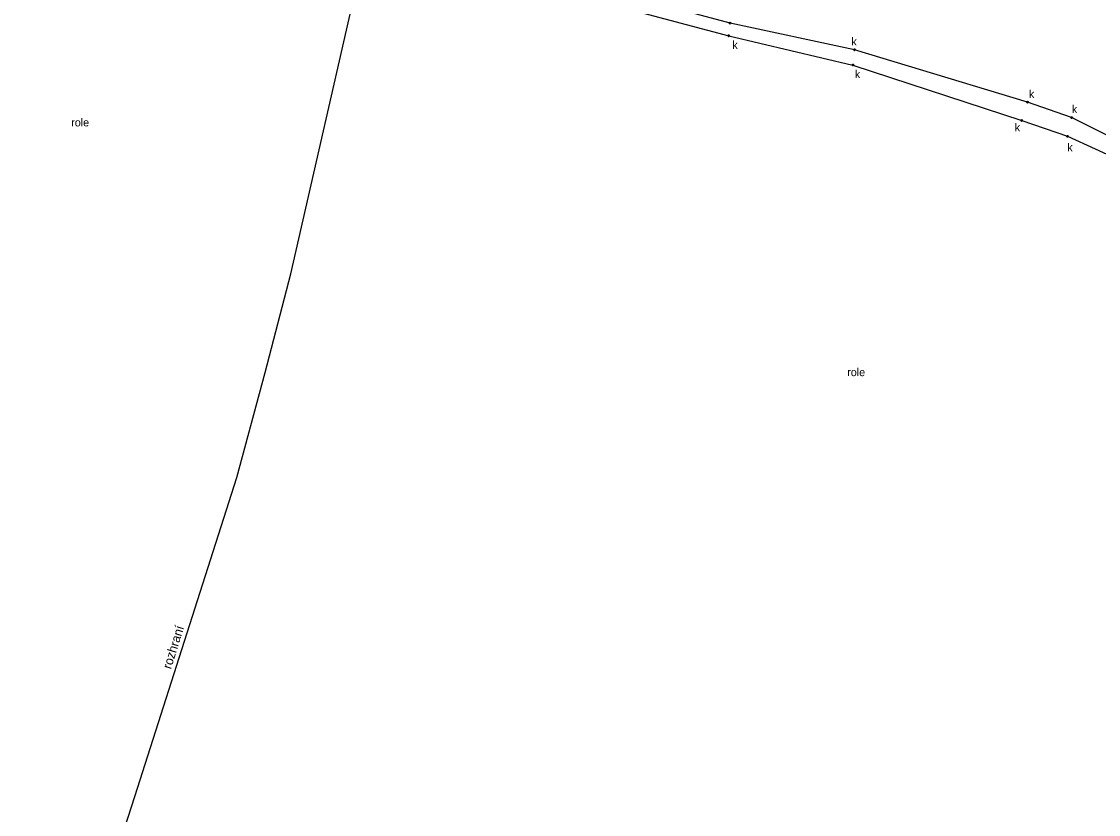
# Model space of a CAD drawing. Extents: x -661586 to -658793, y -1053889 to -1051031.
# Drawn here: x -661409.8 to -661006, y -1052972.2 to -1052674.7 of the extents above; entities that cross this region are included whole.
import ezdxf

# ---------------------------------------------------------------- set-up
doc = ezdxf.new("R2010")
doc.units = 0
for name, color, linetype in [('Vrstva 50', 7, 'Continuous'), ('Vrstva 52', 7, 'Continuous'), ('Vrstva 53', 7, 'Continuous'), ('Vrstva 63', 7, 'Continuous')]:
    doc.layers.add(name, color=color, linetype=linetype)

msp = doc.modelspace()

# ---------------------------------------------------------------- linework, layer by layer
at = {"layer": 'Vrstva 50'}
for p, q in [((-661144.12, -1052675.27), (-661244.57, -1052648.2)), ((-661246.07, -1052652.95), (-661144.61, -1052680)), ((-661097.45, -1052685.24), (-661144.12, -1052675.27)), ((-661144.61, -1052680), (-661098.01, -1052690.99)), ((-661032.59, -1052704.91), (-661097.45, -1052685.24)), ((-661098.01, -1052690.99), (-661034.75, -1052711.78)), ((-661016.03, -1052710.7), (-661032.59, -1052704.91)), ((-660969.23, -1052734.04), (-661016.03, -1052710.7)), ((-661034.75, -1052711.78), (-661017.58, -1052717.73)), ((-661017.58, -1052717.73), (-660971.93, -1052738.59))]:
    msp.add_line(p, q, dxfattribs=at)
for points in [[(-661144.12, -1052674.97), (-661143.9, -1052675.05), (-661143.82, -1052675.27), (-661143.9, -1052675.49), (-661144.12, -1052675.57), (-661144.34, -1052675.49), (-661144.42, -1052675.27), (-661144.34, -1052675.05)], [(-661144.61, -1052679.7), (-661144.39, -1052679.78), (-661144.31, -1052680), (-661144.39, -1052680.22), (-661144.61, -1052680.3), (-661144.83, -1052680.22), (-661144.91, -1052680), (-661144.83, -1052679.78)], [(-661097.45, -1052684.94), (-661097.23, -1052685.02), (-661097.15, -1052685.24), (-661097.23, -1052685.46), (-661097.45, -1052685.54), (-661097.67, -1052685.46), (-661097.75, -1052685.24), (-661097.67, -1052685.02)], [(-661098.01, -1052690.69), (-661097.79, -1052690.77), (-661097.71, -1052690.99), (-661097.79, -1052691.21), (-661098.01, -1052691.29), (-661098.23, -1052691.21), (-661098.31, -1052690.99), (-661098.23, -1052690.77)], [(-661032.59, -1052704.61), (-661032.37, -1052704.69), (-661032.29, -1052704.91), (-661032.37, -1052705.13), (-661032.59, -1052705.21), (-661032.81, -1052705.13), (-661032.89, -1052704.91), (-661032.81, -1052704.69)], [(-661034.75, -1052711.48), (-661034.53, -1052711.56), (-661034.45, -1052711.78), (-661034.53, -1052712), (-661034.75, -1052712.08), (-661034.97, -1052712), (-661035.05, -1052711.78), (-661034.97, -1052711.56)], [(-661016.03, -1052710.4), (-661015.81, -1052710.48), (-661015.73, -1052710.7), (-661015.81, -1052710.92), (-661016.03, -1052711), (-661016.25, -1052710.92), (-661016.33, -1052710.7), (-661016.25, -1052710.48)], [(-661017.58, -1052717.43), (-661017.36, -1052717.51), (-661017.28, -1052717.73), (-661017.36, -1052717.95), (-661017.58, -1052718.03), (-661017.8, -1052717.95), (-661017.88, -1052717.73), (-661017.8, -1052717.51)]]:
    msp.add_lwpolyline(points, close=True, dxfattribs=at)
for points in [[(-661144.2, -1052675.03), (-661144.04, -1052675.03), (-661143.96, -1052675.11), (-661144.28, -1052675.11), (-661144.36, -1052675.19), (-661143.88, -1052675.19), (-661143.88, -1052675.27), (-661144.36, -1052675.27), (-661144.36, -1052675.35), (-661143.88, -1052675.35), (-661143.96, -1052675.43), (-661144.28, -1052675.43), (-661144.2, -1052675.51), (-661144.04, -1052675.51)], [(-661144.69, -1052679.76), (-661144.53, -1052679.76), (-661144.45, -1052679.84), (-661144.77, -1052679.84), (-661144.85, -1052679.92), (-661144.37, -1052679.92), (-661144.37, -1052680), (-661144.85, -1052680), (-661144.85, -1052680.08), (-661144.37, -1052680.08), (-661144.45, -1052680.16), (-661144.77, -1052680.16), (-661144.69, -1052680.24), (-661144.53, -1052680.24)], [(-661097.53, -1052685), (-661097.37, -1052685), (-661097.29, -1052685.08), (-661097.61, -1052685.08), (-661097.69, -1052685.16), (-661097.21, -1052685.16), (-661097.21, -1052685.24), (-661097.69, -1052685.24), (-661097.69, -1052685.32), (-661097.21, -1052685.32), (-661097.29, -1052685.4), (-661097.61, -1052685.4), (-661097.53, -1052685.48), (-661097.37, -1052685.48)], [(-661098.09, -1052690.75), (-661097.93, -1052690.75), (-661097.85, -1052690.83), (-661098.17, -1052690.83), (-661098.25, -1052690.91), (-661097.77, -1052690.91), (-661097.77, -1052690.99), (-661098.25, -1052690.99), (-661098.25, -1052691.07), (-661097.77, -1052691.07), (-661097.85, -1052691.15), (-661098.17, -1052691.15), (-661098.09, -1052691.23), (-661097.93, -1052691.23)], [(-661032.67, -1052704.67), (-661032.51, -1052704.67), (-661032.43, -1052704.75), (-661032.75, -1052704.75), (-661032.83, -1052704.83), (-661032.35, -1052704.83), (-661032.35, -1052704.91), (-661032.83, -1052704.91), (-661032.83, -1052704.99), (-661032.35, -1052704.99), (-661032.43, -1052705.07), (-661032.75, -1052705.07), (-661032.67, -1052705.15), (-661032.51, -1052705.15)], [(-661034.83, -1052711.54), (-661034.67, -1052711.54), (-661034.59, -1052711.62), (-661034.91, -1052711.62), (-661034.99, -1052711.7), (-661034.51, -1052711.7), (-661034.51, -1052711.78), (-661034.99, -1052711.78), (-661034.99, -1052711.86), (-661034.51, -1052711.86), (-661034.59, -1052711.94), (-661034.91, -1052711.94), (-661034.83, -1052712.02), (-661034.67, -1052712.02)], [(-661016.11, -1052710.46), (-661015.95, -1052710.46), (-661015.87, -1052710.54), (-661016.19, -1052710.54), (-661016.27, -1052710.62), (-661015.79, -1052710.62), (-661015.79, -1052710.7), (-661016.27, -1052710.7), (-661016.27, -1052710.78), (-661015.79, -1052710.78), (-661015.87, -1052710.86), (-661016.19, -1052710.86), (-661016.11, -1052710.94), (-661015.95, -1052710.94)], [(-661017.66, -1052717.49), (-661017.5, -1052717.49), (-661017.42, -1052717.57), (-661017.74, -1052717.57), (-661017.82, -1052717.65), (-661017.34, -1052717.65), (-661017.34, -1052717.73), (-661017.82, -1052717.73), (-661017.82, -1052717.81), (-661017.34, -1052717.81), (-661017.42, -1052717.89), (-661017.74, -1052717.89), (-661017.66, -1052717.97), (-661017.5, -1052717.97)]]:
    msp.add_lwpolyline(points, dxfattribs=at)
at = {"layer": 'Vrstva 53'}
for p, q in [((-661308.75, -1052769.27), (-661285.91, -1052669.14)), ((-661318.43, -1052806.37), (-661308.75, -1052769.27)), ((-661329.04, -1052845.75), (-661318.43, -1052806.37)), ((-661367.3, -1052965.42), (-661329.04, -1052845.75)), ((-661409.77, -1053096.75), (-661367.3, -1052965.42))]:
    msp.add_line(p, q, dxfattribs=at)
at = {"layer": 'Vrstva 63'}
for p, q in [((-661144.12, -1052675.27), (-661144.12, -1052675.27)), ((-661144.61, -1052680), (-661144.61, -1052680)), ((-661097.45, -1052685.24), (-661097.45, -1052685.24)), ((-661098.01, -1052690.99), (-661098.01, -1052690.99)), ((-661032.59, -1052704.91), (-661032.59, -1052704.91)), ((-661016.03, -1052710.7), (-661016.03, -1052710.7)), ((-661034.75, -1052711.78), (-661034.75, -1052711.78)), ((-661017.58, -1052717.73), (-661017.58, -1052717.73))]:
    msp.add_line(p, q, dxfattribs=at)

# ---------------------------------------------------------------- texts
at = {"layer": 'Vrstva 50'}
for p in [(-661143.239, -1052684.927), (-661098.587, -1052683.646), (-661097.306, -1052695.907), (-661032.036, -1052703.349), (-661015.932, -1052709.022), (-661037.343, -1052715.854), (-661017.64, -1052723.357)]:
    msp.add_text('k', height=3, dxfattribs=at).set_placement(p)
at = {"layer": 'Vrstva 52'}
for p in [(-661391.129, -1052714.026), (-661100.159, -1052807.722)]:
    msp.add_text('role', height=3, dxfattribs=at).set_placement(p)
at = {"layer": 'Vrstva 53'}
msp.add_text('rozhraní', height=3.4, rotation=72.70834, dxfattribs=at).set_placement((-661353.736, -1052917.844))

doc.saveas('drawing.dxf')
